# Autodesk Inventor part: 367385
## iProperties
Created: 2006-07
Part Number: 367385
Material: A2
Description: Zylinderschraube
Vendor: Autodesk Inc.
Document SubType Name: Modeling
Standard: DIN 912
Designer: I.Baliuc
Standards Organization: DIN
Language: de-DE
Size Designation: M6 x 16
Categories: <MemberInstance Version="R10.0.0"><Categories><Category DisplayName="Schrauben" InternalName="e4da775c-781d-43d5-af7c-5136215cf5a6" Mnemonic="FSTN"><Category Di
Density: 8.08 g/cm^3
Abmessung: M6 x 16
Author: T.Messerschmitt
Comments: DIN 912 - M6 x 16
Revision Number: 367385
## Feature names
1. Körper [Revolution]
2. Loch [Extrusion]
3. Rundung1 [Fillet]
4. Fase1 [Chamfer]
